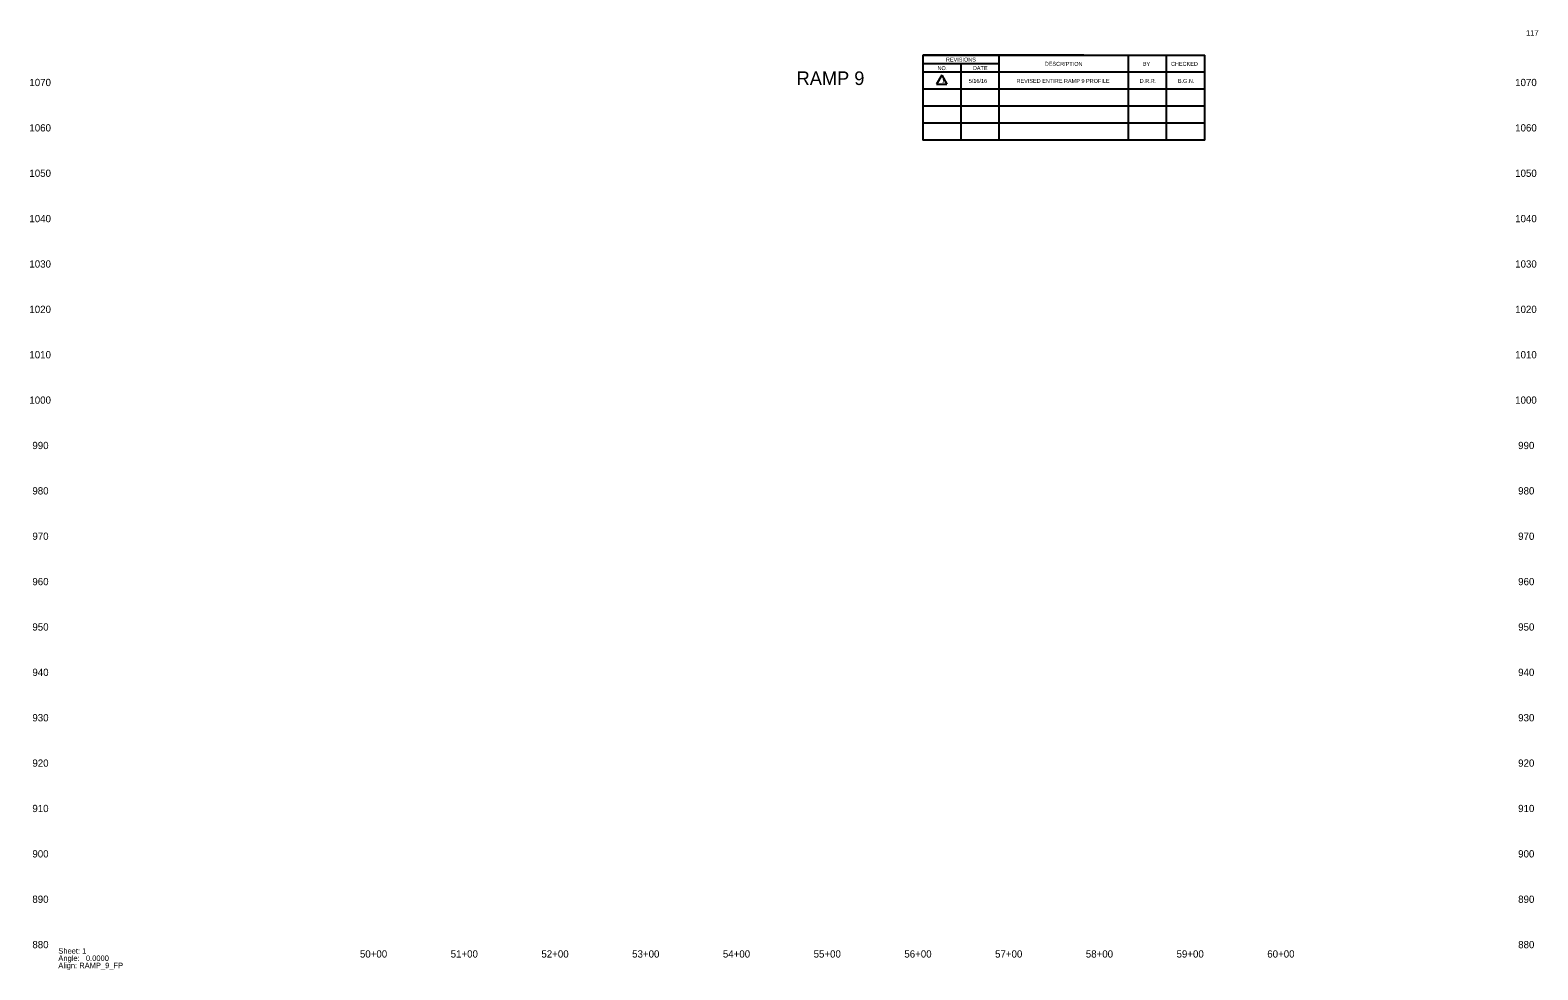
# Model space of a CAD drawing. Extents: x 16972731 to 16974393, y 12549655 to 12550690.
import ezdxf

# ---------------------------------------------------------------- set-up
doc = ezdxf.new("R2010")
doc.units = 0
for name, color, linetype in [('Default', 7, 'Continuous'), ('RD_DDB_ElevTX', 7, 'Continuous'), ('RD_DDB_StaTX', 7, 'Continuous'), ('RD_SHT_TX', 7, 'Continuous')]:
    doc.layers.add(name, color=color, linetype=linetype)

msp = doc.modelspace()

# ---------------------------------------------------------------- linework, layer by layer
at = {"layer": 'RD_SHT_TX'}
for p, q in [((16973715.1, 12550662.7), (16974025.7, 12550662.7)), ((16973892.3, 12550662.7), (16973715.1, 12550662.7)), ((16973715.1, 12550662.7), (16973715.1, 12550569.2)), ((16973799.1, 12550653.3), (16973715.1, 12550653.3)), ((16973757.1, 12550569.2), (16973757.1, 12550653.3)), ((16973799.1, 12550569.2), (16973799.1, 12550662.7)), ((16973941.7, 12550569.2), (16973941.7, 12550662.7)), ((16973983.7, 12550569.2), (16973983.7, 12550662.7)), ((16974025.7, 12550569.2), (16974025.7, 12550662.7)), ((16974025.7, 12550644), (16973715.1, 12550644)), ((16973735.8, 12550641), (16973730.1, 12550630.9)), ((16973735.8, 12550641), (16973741.5, 12550630.9)), ((16974025.7, 12550625.3), (16973715.1, 12550625.3)), ((16973730.1, 12550630.9), (16973741.5, 12550630.9)), ((16974025.7, 12550606.6), (16973715.1, 12550606.6)), ((16974025.7, 12550587.9), (16973715.1, 12550587.9)), ((16974025.7, 12550569.2), (16973715.1, 12550569.2))]:
    msp.add_line(p, q, dxfattribs=at)

# ---------------------------------------------------------------- texts
at = {"layer": 'Default'}
for s, p in [('Angle:   0.0000', (16972762.2, 12549664.8)), ('Sheet: 1', (16972762.2, 12549672.8)), ('Align: RAMP_9_FP', (16972762.2, 12549656.8))]:
    msp.add_text(s, height=6, dxfattribs=at).set_placement(p)
at = {"layer": 'RD_DDB_ElevTX'}
for s, p in [('1070', (16972730.3, 12550628.8)), ('1070', (16974367.8, 12550628.8)), ('1060', (16972730.3, 12550578.8)), ('1060', (16974367.8, 12550578.8)), ('1050', (16972730.3, 12550528.8)), ('1050', (16974367.8, 12550528.8)), ('1040', (16972730.3, 12550478.8)), ('1040', (16974367.8, 12550478.8)), ('1030', (16972730.3, 12550428.8)), ('1030', (16974367.8, 12550428.8)), ('1020', (16972730.3, 12550378.8)), ('1020', (16974367.8, 12550378.8)), ('1010', (16972730.3, 12550328.8)), ('1010', (16974367.8, 12550328.8)), ('1000', (16972730.3, 12550278.8)), ('1000', (16974367.8, 12550278.8)), ('990', (16972733.6, 12550228.8)), ('990', (16974371.1, 12550228.8)), ('980', (16972733.6, 12550178.8)), ('980', (16974371.1, 12550178.8)), ('970', (16972733.6, 12550128.8)), ('970', (16974371.1, 12550128.8)), ('960', (16972733.6, 12550078.8)), ('960', (16974371.1, 12550078.8)), ('950', (16972733.6, 12550028.8)), ('950', (16974371.1, 12550028.8)), ('940', (16972733.6, 12549978.8)), ('940', (16974371.1, 12549978.8)), ('930', (16972733.6, 12549928.8)), ('930', (16974371.1, 12549928.8)), ('920', (16972733.6, 12549878.8)), ('920', (16974371.1, 12549878.8)), ('910', (16972733.6, 12549828.8)), ('910', (16974371.1, 12549828.8)), ('900', (16972733.6, 12549778.8)), ('900', (16974371.1, 12549778.8)), ('890', (16972733.6, 12549728.8)), ('890', (16974371.1, 12549728.8)), ('880', (16972733.6, 12549678.8)), ('880', (16974371.1, 12549678.8))]:
    msp.add_text(s, height=8, dxfattribs=at).set_placement(p)
at = {"layer": 'RD_DDB_StaTX'}
for s, p in [('50+00', (16973094.6, 12549668.5)), ('51+00', (16973194.6, 12549668.5)), ('52+00', (16973294.6, 12549668.5)), ('53+00', (16973394.6, 12549668.5)), ('54+00', (16973494.6, 12549668.5)), ('55+00', (16973594.6, 12549668.5)), ('56+00', (16973694.6, 12549668.5)), ('57+00', (16973794.6, 12549668.5)), ('58+00', (16973894.6, 12549668.5)), ('59+00', (16973994.6, 12549668.5)), ('60+00', (16974094.6, 12549668.5))]:
    msp.add_text(s, height=8, dxfattribs=at).set_placement(p)
at = {"layer": 'RD_SHT_TX'}
for s, height, p in [('117', 6, (16974379.8, 12550684.4)), ('NO.', 4.4, (16973731.1, 12550646.4)), ('REVISIONS', 4.4, (16973740.4, 12550655.8)), ('CHECKED', 4.4, (16973988.4, 12550651.1)), ('RAMP 9', 15, (16973575.9, 12550630)), ('1', 4.4, (16973735.8, 12550632.5)), ('5/16/16', 4.4, (16973765.6, 12550632.3)), ('REVISED ENTIRE RAMP 9 PROFILE ', 4.4, (16973818.2, 12550632.3)), ('D.R.R.', 4.4, (16973954, 12550632.3)), ('B.G.N.', 4.4, (16973996.1, 12550632.3))]:
    msp.add_text(s, height=height, dxfattribs=at).set_placement(p)
for s, height, p in [('DATE', 4.41, (16973770.1, 12550646.5)), ('DESCRIPTION', 4.408, (16973849.4, 12550651.2)), ('BY', 4.41, (16973957.4, 12550651.1))]:
    msp.add_text(s, height=height, rotation=359.7246, dxfattribs=at).set_placement(p)

doc.saveas('drawing.dxf')
